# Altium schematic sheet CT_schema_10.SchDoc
size 274 x 160 mm
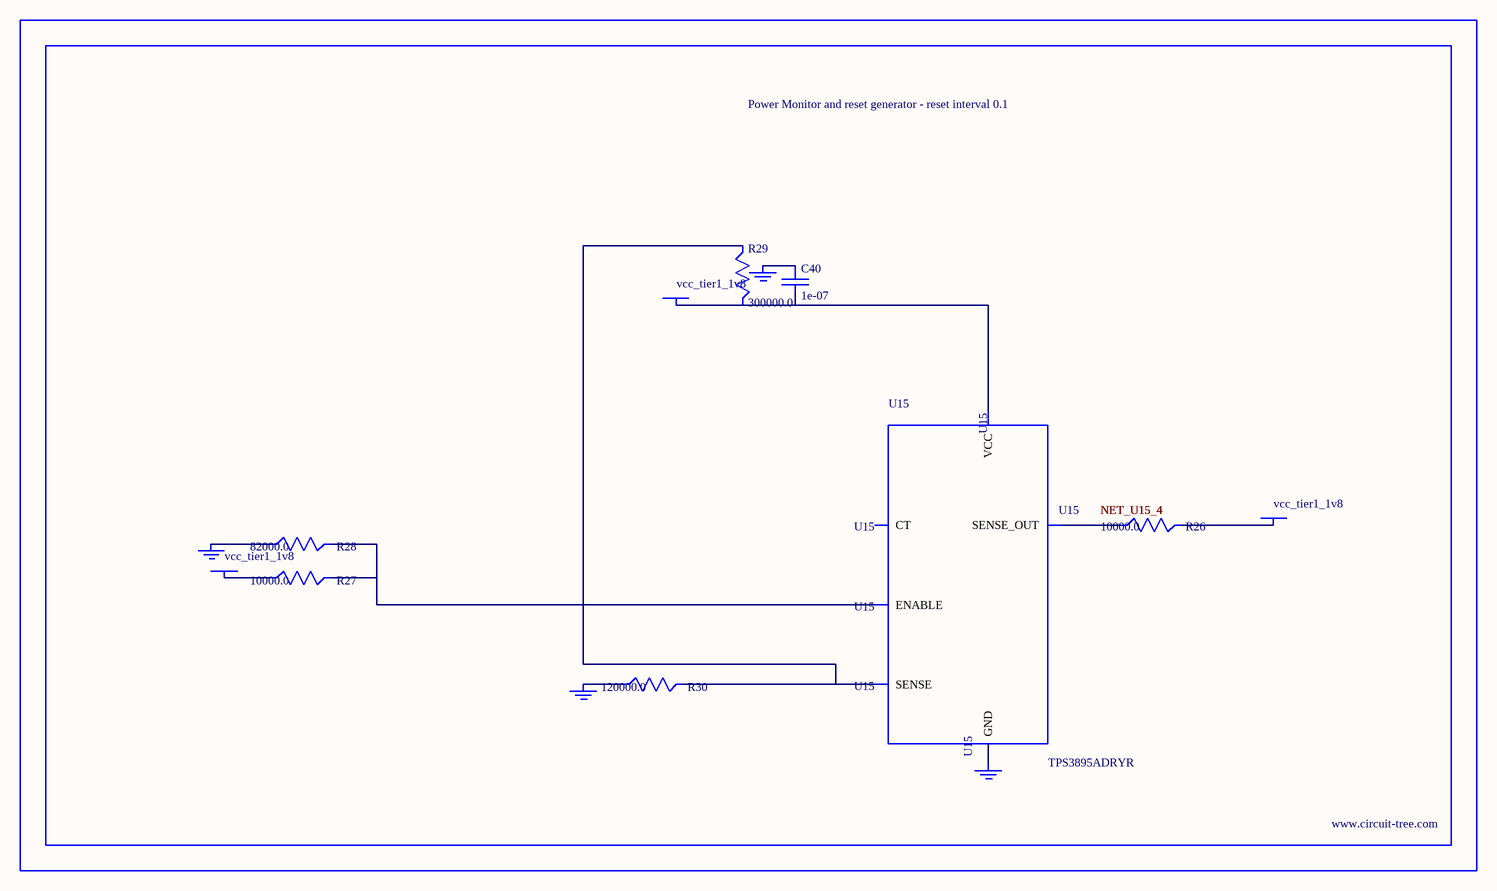
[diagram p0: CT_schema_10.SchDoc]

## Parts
BORDER9  (no value)
C40  1e-07  [C0402]
GND_INSTANCE_9_0  (no value)
GND_INSTANCE_9_1  (no value)
GND_INSTANCE_9_2  (no value)
GND_INSTANCE_9_3  (no value)
POWER_INSTANCE_9_0  vcc_tier1_1v8
POWER_INSTANCE_9_1  vcc_tier1_1v8
POWER_INSTANCE_9_2  vcc_tier1_1v8
R26  10000.0  [R0603]
R27  10000.0  [R0603]
R28  82000.0  [R0603]
R29  300000.0  [R0603]
R30  120000.0  [R0603]
U15  TPS3895ADRYR  [SON-6]

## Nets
NetC40_1: C40.1 GND_INSTANCE_9_2.0(GND)
NetC40_2: C40.2 POWER_INSTANCE_9_2.0(PWR) R29.2 U15.6(VCC)
NetGND_INSTANCE_9_0_0: GND_INSTANCE_9_0.0(GND) R28.1
NetGND_INSTANCE_9_1_0: GND_INSTANCE_9_1.0(GND) R30.1
NetGND_INSTANCE_9_3_0: GND_INSTANCE_9_3.0(GND) U15.2(GND)
NetPOWER_INSTANCE_9_0_0: POWER_INSTANCE_9_0.0(PWR) R27.1
NetPOWER_INSTANCE_9_1_0: POWER_INSTANCE_9_1.0(PWR) R26.2
NetR26_1: R26.1 U15.4(SENSE_OUT)
NetR27_2: R27.2 R28.2 U15.1(ENABLE)
NetR29_1: R29.1 R30.2 U15.3(SENSE)

Not connected (* = marked no-connect by the designer): U15 5(CT)

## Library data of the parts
BORDER9 = BORDER_PAGE9
C40 = C0402C104K3RACTU
GND_INSTANCE_9_0-GND_INSTANCE_9_3 = GND
POWER_INSTANCE_9_0-POWER_INSTANCE_9_2 = PWR
R26 R27 = RC0603JR-0710KL
R28 = RC0603JR-0782KL
R29 = RC0603JR-07300KL
R30 = RC0603JR-07120KL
